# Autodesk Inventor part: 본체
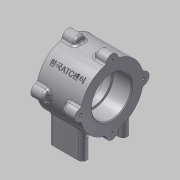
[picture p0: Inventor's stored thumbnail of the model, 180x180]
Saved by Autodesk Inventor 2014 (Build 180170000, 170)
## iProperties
Created: 2015-03
Part Number: 본체
Material: 알루미늄 6061
Document SubType Name: Modeling
Designer: MYHOME
Mass: 450.776 g
Surface Area: 332.745 cm^2
Volume: 166.338 cm^3
Density: 2.71 g/cm^3
Appearance: 알루미늄 - 평지
Author: MYHOME
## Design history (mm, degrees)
sketch "스케치2"
  geometry: C1 r 37 at (0, 0); 1 further point
  constraints: 1 centre point, 1 coincident
  dimensions: "d0" = 74 diameter of C1
extrude "돌출1" new body sketch "스케치2" stored distance "d1" = 52; taper "d2" = 0 deg
sketch "스케치3"
  geometry: C1 r 37 at (0, 0) reference; C2 r 23.5 at (0, 0)
  constraints: 1 centre point, 1 coincident
  dimensions: "d3" = 47 diameter of C2
extrude "돌출2" cut sketch "스케치3" distance "d4" = 22; taper "d5" = 0 deg
sketch "스케치4" dims "d6" = 74
  geometry: L1 (0, 0)-(0, 37); C1 r 23.5 at (0, 0) reference; C2 r 37 at (0, 0) reference; C3 r 7 at (0, 37); 1 further point
  constraints: 2 coincident, 2 end point, 2 vertical alignment, 1 centre point, 1 midpoint, 1 vertical, 2 other
  dimensions: "d7" = 7 radius of C3
extrude "돌출3" join sketch "스케치4" distance "d8" = 15; taper "d9" = 0 deg
fillet "모깎기2" dims "d11" = 3
fillet "모깎기3" dims "d12" = 3
sketch "스케치5"
  geometry: A1 r 7 centre (0, 37) between (6.889, 38.239) and (-6.889, 38.239) reference; 1 further point
  constraints: 1 coincident
hole "구멍1" sketch "스케치5" at (0, 37) diameter "d13" = 3.242; stored, may be unused: countersink angle "d17" = 90 deg, drill point angle "d19" = 118 deg; dims "d14" = 8, "d15" = 4, "d16" = 2, "d18" = 11
sketch "스케치6"
  geometry: C1 r 23.5 at (0, 0) reference; C2 r 21 at (0, 0)
  constraints: 1 centre point, 1 coincident
  dimensions: "d23" = 42 diameter of C2
extrude "돌출4" cut sketch "스케치6" stored distance "d24" = 15; taper "d25" = 0 deg
sketch "스케치7"
  geometry: L1 (-29, -22.978)-(-29, -56); L2 (-29, -56)-(-19, -56); L3 (-19, -56)-(-19, -31.749); L4 (19, -31.749)-(19, -56); L5 (19, -56)-(29, -56); L6 (29, -56)-(29, -22.978); L7 (0, 0)-(0, -23.5); C1 r 1.621 at (0, -37) reference; C2 r 1.621 at (-37, 0) reference; C3 r 1.621 at (0, 37) reference; C4 r 1.621 at (37, 0) reference; A1 r 37 centre (0, 0) between (-35.863, -9.104) and (-9.104, -35.863) reference; A2 r 3 centre (-38.77, -9.842) between (-35.863, -9.104) and (-38.239, -6.889) reference; A3 r 7 centre (-37, 0) between (-38.239, 6.889) and (-38.239, -6.889) reference; A4 r 3 centre (-38.77, 9.842) between (-38.239, 6.889) and (-35.863, 9.104) reference; A5 r 37 centre (0, 0) between (-9.104, 35.863) and (-35.863, 9.104) reference; A6 r 3 centre (-9.842, 38.77) between (-9.104, 35.863) and (-6.889, 38.239) reference; A7 r 7 centre (0, 37) between (6.889, 38.239) and (-6.889, 38.239) reference; A8 r 3 centre (9.842, 38.77) between (6.889, 38.239) and (9.104, 35.863) reference; A9 r 37 centre (0, 0) between (35.863, 9.104) and (9.104, 35.863) reference; A10 r 3 centre (38.77, 9.842) between (35.863, 9.104) and (38.239, 6.889) reference; A11 r 7 centre (37, 0) between (38.239, -6.889) and (38.239, 6.889) reference; A12 r 3 centre (38.77, -9.842) between (38.239, -6.889) and (35.863, -9.104) reference; A13 r 37 centre (0, 0) between (9.104, -35.863) and (35.863, -9.104) reference; A14 r 3 centre (9.842, -38.77) between (9.104, -35.863) and (6.889, -38.239) reference; A15 r 7 centre (0, -37) between (-6.889, -38.239) and (6.889, -38.239) reference; A16 r 3 centre (-9.842, -38.77) between (-6.889, -38.239) and (-9.104, -35.863) reference; 1 further point
  constraints: 14 end point, 4 parallel, 4 point on circle, 2 perpendicular, 1 collinear, 1 vertical, 1 vertical alignment, 2 other
  dimensions: "d26" = 10 distance of L1.end L2.end; "d27" = 10 distance of L4.end L5.end; "d28" = 19 horizontal distance of L2.end point (0, 0); "d29" = 56 distance from line of L2 point (0, 0)
extrude "돌출5" join sketch "스케치7" stored distance "d30" = 40; taper "d31" = 0 deg
fillet "모깎기4" dims "d32" = 5
sketch "스케치10"
  geometry: L1 (30, -38)-(0, -38) reference; L2 (30, -48)-(0, -48) reference; A1 r 5 centre (0, 5) between (0, 10) and (0, 0) reference; A2 r 5 centre (30, 5) between (30, 0) and (30, 10) reference; A3 r 5 centre (30, -43) between (30, -48) and (30, -38) reference; A4 r 5 centre (0, -43) between (0, -38) and (0, -48) reference; 5 further points
  constraints: 4 coincident
hole "구멍2" sketch "스케치10" at (0, 5), (30, 5), (30, -43), (0, -43) diameter "d33" = 4.134; stored, may be unused: countersink angle "d37" = 90 deg, drill point angle "d39" = 118 deg; dims "d34" = 6, "d35" = 4, "d36" = 2, "d38" = 8
chamfer "모따기1" distance "d40" = 1; stored, may be unused: second distance "d41" = 2, angle "d42" = 45 deg
fillet "모깎기5" dims "d43" = 0.3
fillet "모깎기6" dims "d44" = 3
sketch "스케치11"
  geometry: L1 (0, 0)-(-26.163, 26.163); L2 (0, 0)-(-24.5, 0); C1 r 1.621 at (37, 0) reference; C2 r 1.621 at (0, 37) reference; C3 r 1.621 at (-37, 0) reference; C4 r 1.621 at (0, -37) reference; A1 r 37 centre (0, 0) between (-35.863, -9.104) and (-9.104, -35.863) reference; A2 r 3 centre (-38.77, -9.842) between (-35.863, -9.104) and (-38.239, -6.889) reference; A3 r 7 centre (-37, 0) between (-38.239, 6.889) and (-38.239, -6.889) reference; A4 r 3 centre (-38.77, 9.842) between (-38.239, 6.889) and (-35.863, 9.104) reference; A5 r 37 centre (0, 0) between (-9.104, 35.863) and (-35.863, 9.104) reference; A6 r 3 centre (-9.842, 38.77) between (-9.104, 35.863) and (-6.889, 38.239) reference; A7 r 7 centre (0, 37) between (6.889, 38.239) and (-6.889, 38.239) reference; A8 r 3 centre (9.842, 38.77) between (6.889, 38.239) and (9.104, 35.863) reference; A9 r 37 centre (0, 0) between (35.863, 9.104) and (9.104, 35.863) reference; A10 r 3 centre (38.77, 9.842) between (35.863, 9.104) and (38.239, 6.889) reference; A11 r 7 centre (37, 0) between (38.239, -6.889) and (38.239, 6.889) reference; A12 r 3 centre (38.77, -9.842) between (38.239, -6.889) and (35.863, -9.104) reference; A13 r 37 centre (0, 0) between (9.104, -35.863) and (35.863, -9.104) reference; A14 r 3 centre (9.842, -38.77) between (9.104, -35.863) and (6.889, -38.239) reference; A15 r 7 centre (0, -37) between (-6.889, -38.239) and (6.889, -38.239) reference; A16 r 3 centre (-9.842, -38.77) between (-6.889, -38.239) and (-9.104, -35.863) reference; 2 further points
  constraints: 4 end point, 1 coincident, 1 horizontal, 1 horizontal alignment, 1 point on circle, 1 other
  dimensions: "d45" = 45 deg angle of L1 L2
  node "투영된 루프3"
node "작업 평면2"
  node "작업 평면1"
sketch "스케치12"
  geometry: L1 (-26, 18.921)-(-26, -18.921) reference; 2 further points
  constraints: 1 coincident, 1 other
feature "엠보싱1" sketch "스케치12" dims "d48" = 0.5, "d49" = 0
node "솔리드1"
pattern_circular "원형 패턴1" dims "d21" = 360 deg
mirror "대칭1"
node "투영된 루프1"
node "투영된 루프2"
other parameters: "d46" = 0.5
